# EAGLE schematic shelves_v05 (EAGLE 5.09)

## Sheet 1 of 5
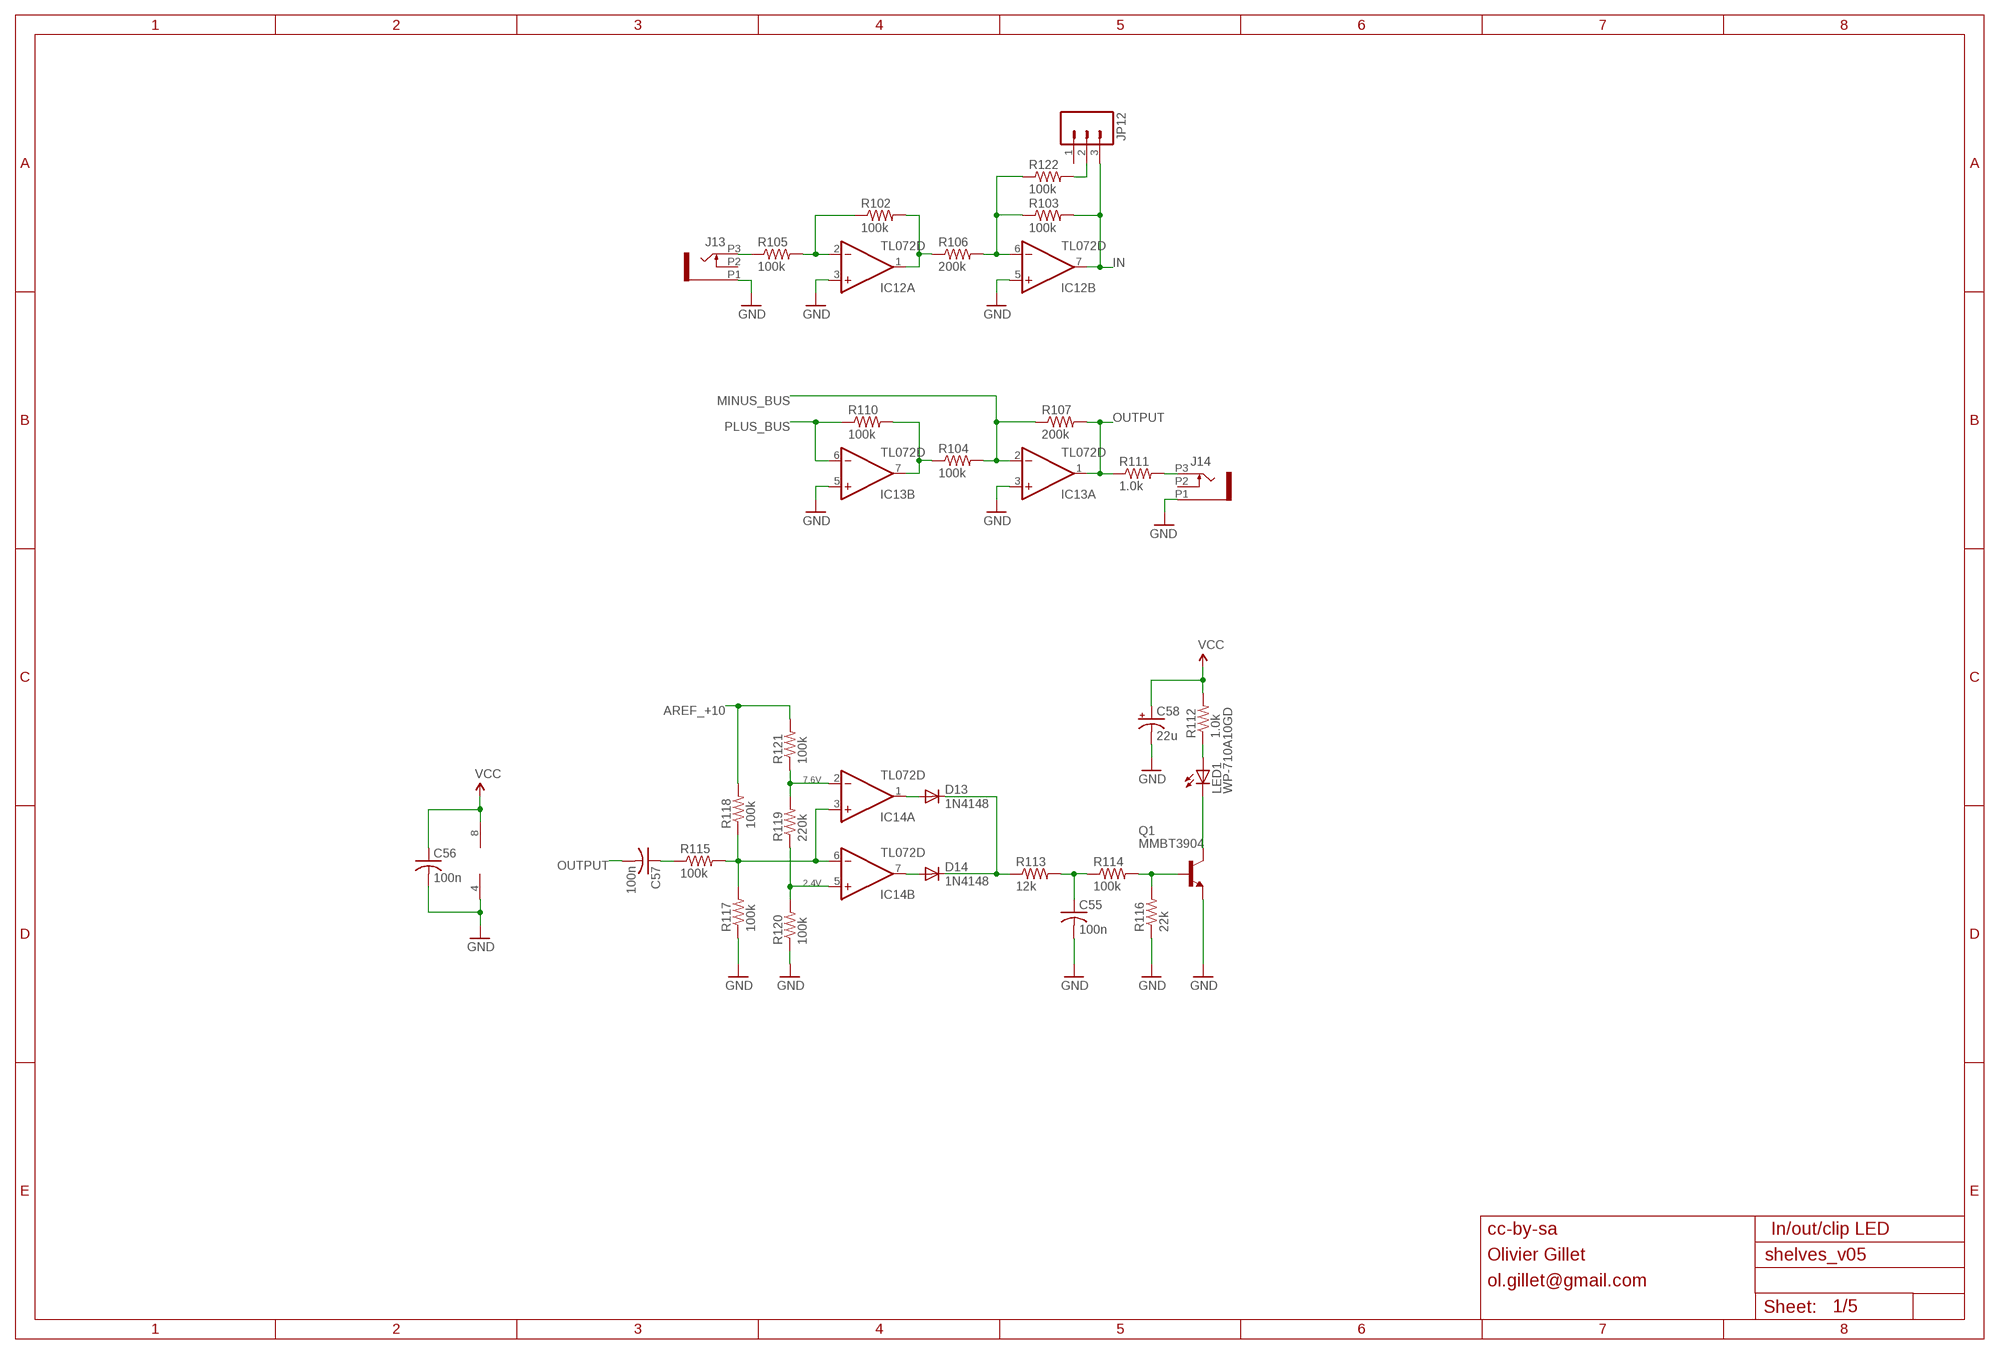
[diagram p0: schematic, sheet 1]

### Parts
C55  100n  C-USC0603  [C0603]
C56  100n  C-USC0603  [C0603]
C57  100n  C-USC0603  [C0603]
C58  22u  CPOL-USC  [PANASONIC_C]
D13  1N4148  DIODE-SOD323-W  [SOD323-W]
D14  1N4148  DIODE-SOD323-W  [SOD323-W]
IC12  TL072D  [SO08]
IC13  TL072D  [SO08]
IC14  TL072D  [SO08]
J13  PJ301_THONKICONN6  [WQP_PJ_301M6]
J14  PJ301_THONKICONN6  [WQP_PJ_301M6]
JP12  M03PTH  [1X03]
LED1  WP-710A10GD  LED3MM  [LED3MM]
Q1  MMBT3904  MMBT3904LT1-NPN-SOT23-BEC  [SOT23-BEC]
R102  100k  R-US_R0603  [R0603]
R103  100k  R-US_R0603  [R0603]
R104  100k  R-US_R0603  [R0603]
R105  100k  R-US_R0603  [R0603]
R106  200k  R-US_R0603  [R0603]
R107  200k  R-US_R0603  [R0603]
R110  100k  R-US_R0603  [R0603]
R111  1.0k  R-US_R0603  [R0603]
R112  1.0k  R-US_R0603  [R0603]
R113  12k  R-US_R0603  [R0603]
R114  100k  R-US_R0603  [R0603]
R115  100k  R-US_R0603  [R0603]
R116  22k  R-US_R0603  [R0603]
R117  100k  R-US_R0603  [R0603]
R118  100k  R-US_R0603  [R0603]
R119  220k  R-US_R0603  [R0603]
R120  100k  R-US_R0603  [R0603]
R121  100k  R-US_R0603  [R0603]
R122  100k  R-US_R0603  [R0603]

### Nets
AREF_+10: R118.2 R121.2 ; also sheet 2,3,4,5
GND: C55.2 C56.2 C58.- IC12.3(A:+IN) IC12.5(B:+IN) IC13.3(A:+IN) IC13.5(B:+IN) IC14.4(P:V-) J13.P1 J14.P1 Q1.E R116.1 R117.1 R120.1 ; also sheet 2,3,4,5
IN: IC12.7(B:OUT) JP12.3 R103.2 ; also sheet 2,3,4
IN_INV: IC12.1(A:OUT) R102.2 R106.1
IN_INV1: IC13.7(B:OUT) R104.1 R110.2
J_IN: J13.P3 R105.1
MINUS_BUS: IC13.2(A:-IN) R104.2 R107.1 ; also sheet 2,3,4
N$6: JP12.2 R122.2
N$9: IC12.2(A:-IN) R102.1 R105.2
N$30: IC12.6(B:-IN) R103.1 R106.2 R122.1
N$60: LED1.K(C) Q1.C
N$93: J14.P3 R111.2
N$94: C57.1 R115.1
N$96: IC14.3(A:+IN) IC14.6(B:-IN) R115.2 R117.2 R118.1
N$97: IC14.2(A:-IN) R119.2 R121.1
N$98: C55.1 R113.2 R114.1
N$99: IC14.5(B:+IN) R119.1 R120.2
N$100: D13.A IC14.1(A:OUT)
N$101: D14.A IC14.7(B:OUT)
N$102: D13.C D14.C R113.1
N$103: LED1.A R112.1
N$104: Q1.B R114.2 R116.2
OUTPUT: C57.2 IC13.1(A:OUT) R107.2 R111.1
PLUS_BUS: IC13.6(B:-IN) R110.1 ; also sheet 2,3,4
VCC: C56.1 C58.+ IC14.8(P:V+) R112.2 ; also sheet 2,3,4,5
Unconnected: J13.P2 J14.P2 JP12.1

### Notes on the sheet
- 7.6V
- 2.4V
- cc-by-sa | In/out/clip LED
- Olivier Gillet
- ol.gillet@gmail.com

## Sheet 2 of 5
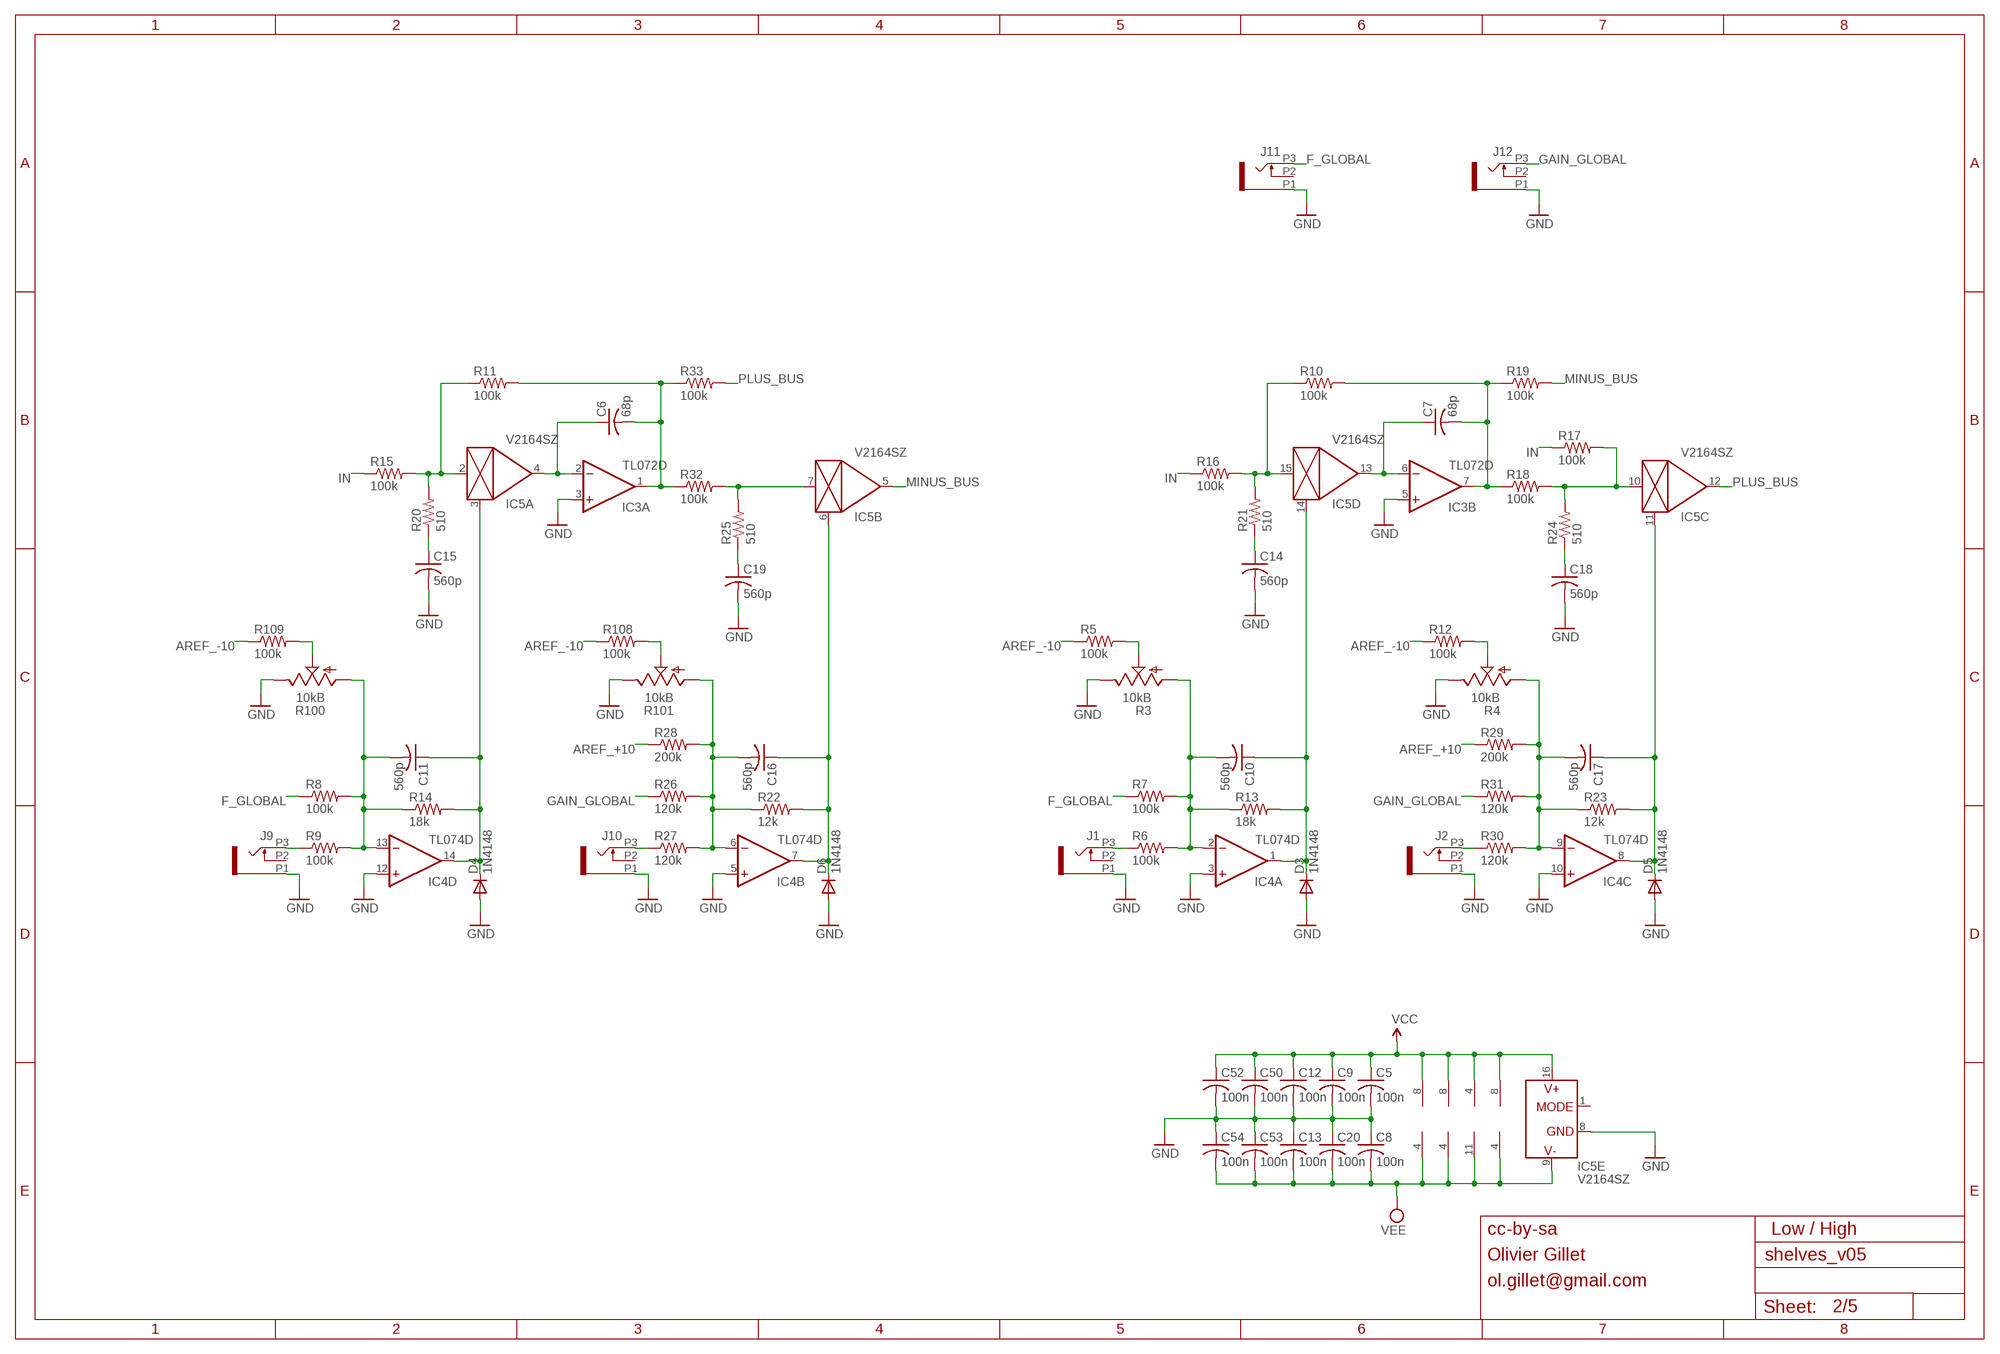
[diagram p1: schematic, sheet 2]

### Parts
C5  100n  C-USC0603  [C0603]
C6  68p  C-USC0603  [C0603]
C7  68p  C-USC0603  [C0603]
C8  100n  C-USC0603  [C0603]
C9  100n  C-USC0603  [C0603]
C10  560p  C-USC0603  [C0603]
C11  560p  C-USC0603  [C0603]
C12  100n  C-USC0603  [C0603]
C13  100n  C-USC0603  [C0603]
C14  560p  C-USC0603  [C0603]
C15  560p  C-USC0603  [C0603]
C16  560p  C-USC0603  [C0603]
C17  560p  C-USC0603  [C0603]
C18  560p  C-USC0603  [C0603]
C19  560p  C-USC0603  [C0603]
C20  100n  C-USC0603  [C0603]
C50  100n  C-USC0603  [C0603]
C52  100n  C-USC0603  [C0603]
C53  100n  C-USC0603  [C0603]
C54  100n  C-USC0603  [C0603]
D3  1N4148  DIODE-SOD323-W  [SOD323-W]
D4  1N4148  DIODE-SOD323-W  [SOD323-W]
D5  1N4148  DIODE-SOD323-W  [SOD323-W]
D6  1N4148  DIODE-SOD323-W  [SOD323-W]
IC3  TL072D  [SO08]
IC4  TL074D  [SO14]
IC5  V2164SZ  SSM2164S  [SOIC16N]
J1  PJ301_THONKICONN6  [WQP_PJ_301M6]
J2  PJ301_THONKICONN6  [WQP_PJ_301M6]
J9  PJ301_THONKICONN6  [WQP_PJ_301M6]
J10  PJ301_THONKICONN6  [WQP_PJ_301M6]
J11  PJ301_THONKICONN6  [WQP_PJ_301M6]
J12  PJ301_THONKICONN6  [WQP_PJ_301M6]
R3  10kB  POT_USVERTICAL_PS  [ALPS_POT_VERTICAL_PS]
R4  10kB  POT_USVERTICAL_PS  [ALPS_POT_VERTICAL_PS]
R5  100k  R-US_R0603  [R0603]
R6  100k  R-US_R0603  [R0603]
R7  100k  R-US_R0603  [R0603]
R8  100k  R-US_R0603  [R0603]
R9  100k  R-US_R0603  [R0603]
R10  100k  R-US_R0603  [R0603]
R11  100k  R-US_R0603  [R0603]
R12  100k  R-US_R0603  [R0603]
R13  18k  R-US_R0603  [R0603]
R14  18k  R-US_R0603  [R0603]
R15  100k  R-US_R0603  [R0603]
R16  100k  R-US_R0603  [R0603]
R17  100k  R-US_R0603  [R0603]
R18  100k  R-US_R0603  [R0603]
R19  100k  R-US_R0603  [R0603]
R20  510  R-US_R0603  [R0603]
R21  510  R-US_R0603  [R0603]
R22  12k  R-US_R0603  [R0603]
R23  12k  R-US_R0603  [R0603]
R24  510  R-US_R0603  [R0603]
R25  510  R-US_R0603  [R0603]
R26  120k  R-US_R0603  [R0603]
R27  120k  R-US_R0603  [R0603]
R28  200k  R-US_R0603  [R0603]
R29  200k  R-US_R0603  [R0603]
R30  120k  R-US_R0603  [R0603]
R31  120k  R-US_R0603  [R0603]
R32  100k  R-US_R0603  [R0603]
R33  100k  R-US_R0603  [R0603]
R100  10kB  POT_USVERTICAL_PS  [ALPS_POT_VERTICAL_PS]
R101  10kB  POT_USVERTICAL_PS  [ALPS_POT_VERTICAL_PS]
R108  100k  R-US_R0603  [R0603]
R109  100k  R-US_R0603  [R0603]

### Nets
AREF_+10: R28.1 R29.1 ; also sheet 1,3,4,5
AREF_-10: R5.1 R12.1 R108.1 R109.1 ; also sheet 3,4,5
F_GLOBAL: J11.P3 R7.1 R8.1 ; also sheet 3,4
GAIN_GLOBAL: J12.P3 R26.1 R31.1 ; also sheet 3,4
GND: C5.2 C8.1 C9.2 C12.2 C13.1 C14.2 C15.2 C18.2 C19.2 C20.1 C50.2 C52.2 C53.1 C54.1 D3.A D4.A D5.A D6.A IC3.3(A:+IN) IC3.5(B:+IN) IC4.3(A:+IN) IC4.5(B:+IN) IC4.10(C:+IN) IC4.12(D:+IN) IC5.8(E:GND) J1.P1 J2.P1 J9.P1 J10.P1 J11.P1 J12.P1 R3.P$1(E) R4.P$1(E) R100.P$1(E) R101.P$1(E) ; also sheet 1,3,4,5
IN: R15.1 R16.1 R17.1 ; also sheet 1,3,4
J_HF_CV: J2.P3 R30.1
J_HF_F: J1.P3 R6.1
J_LF_CV: J10.P3 R27.1
J_LF_F: J9.P3 R9.1
LP: C6.2 IC3.1(A:OUT) R11.2 R32.1 R33.1
LP1: C7.2 IC3.7(B:OUT) R10.2 R18.1 R19.1
MINUS_BUS: IC5.5(B:OUT) R19.2 ; also sheet 1,3,4
N$1: IC5.2(A:IN) R11.1 R15.2 R20.2
N$2: C19.1 R25.1
N$3: C11.1 D4.C IC4.14(D:OUT) IC5.3(A:CTRL) R14.2
N$4: C6.1 IC3.2(A:-IN) IC5.4(A:OUT)
N$5: C14.1 R21.1
N$7: C16.1 D6.C IC4.7(B:OUT) IC5.6(B:CTRL) R22.2
N$10: C15.1 R20.1
N$12: R100.P$2(S) R109.2
N$13: C16.2 IC4.6(B:-IN) R22.1 R26.2 R27.2 R28.2 R101.P$3(A)
N$15: R101.P$2(S) R108.2
N$16: IC5.15(D:IN) R10.1 R16.2 R21.2
N$17: IC5.7(B:IN) R25.2 R32.2
N$18: C11.2 IC4.13(D:-IN) R8.2 R9.2 R14.1 R100.P$3(A)
N$19: C7.1 IC3.6(B:-IN) IC5.13(D:OUT)
N$21: R3.P$2(S) R5.2
N$22: C17.1 D5.C IC4.8(C:OUT) IC5.11(C:CTRL) R23.2
N$23: C17.2 IC4.9(C:-IN) R4.P$3(A) R23.1 R29.2 R30.2 R31.2
N$26: R4.P$2(S) R12.2
N$27: C10.2 IC4.2(A:-IN) R3.P$3(A) R6.2 R7.2 R13.1
N$28: C18.1 R24.1
N$29: IC5.10(C:IN) R17.2 R18.2 R24.2
N$31: C10.1 D3.C IC4.1(A:OUT) IC5.14(D:CTRL) R13.2
PLUS_BUS: IC5.12(C:OUT) R33.2 ; also sheet 1,3,4
VCC: C5.1 C9.1 C12.1 C50.1 C52.1 IC3.8(P:V+) IC4.4(P:V+) IC5.16(E:V+) IC12.8(P:V+) IC13.8(P:V+) ; also sheet 1,3,4,5
VEE: C8.2 C13.2 C20.2 C53.2 C54.2 IC3.4(P:V-) IC4.11(P:V-) IC5.9(E:V-) IC12.4(P:V-) IC13.4(P:V-) ; also sheet 3,4,5
Unconnected: IC5.1(E:MODE) J1.P2 J2.P2 J9.P2 J10.P2 J11.P2 J12.P2

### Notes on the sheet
- cc-by-sa | Low / High
- Olivier Gillet
- ol.gillet@gmail.com

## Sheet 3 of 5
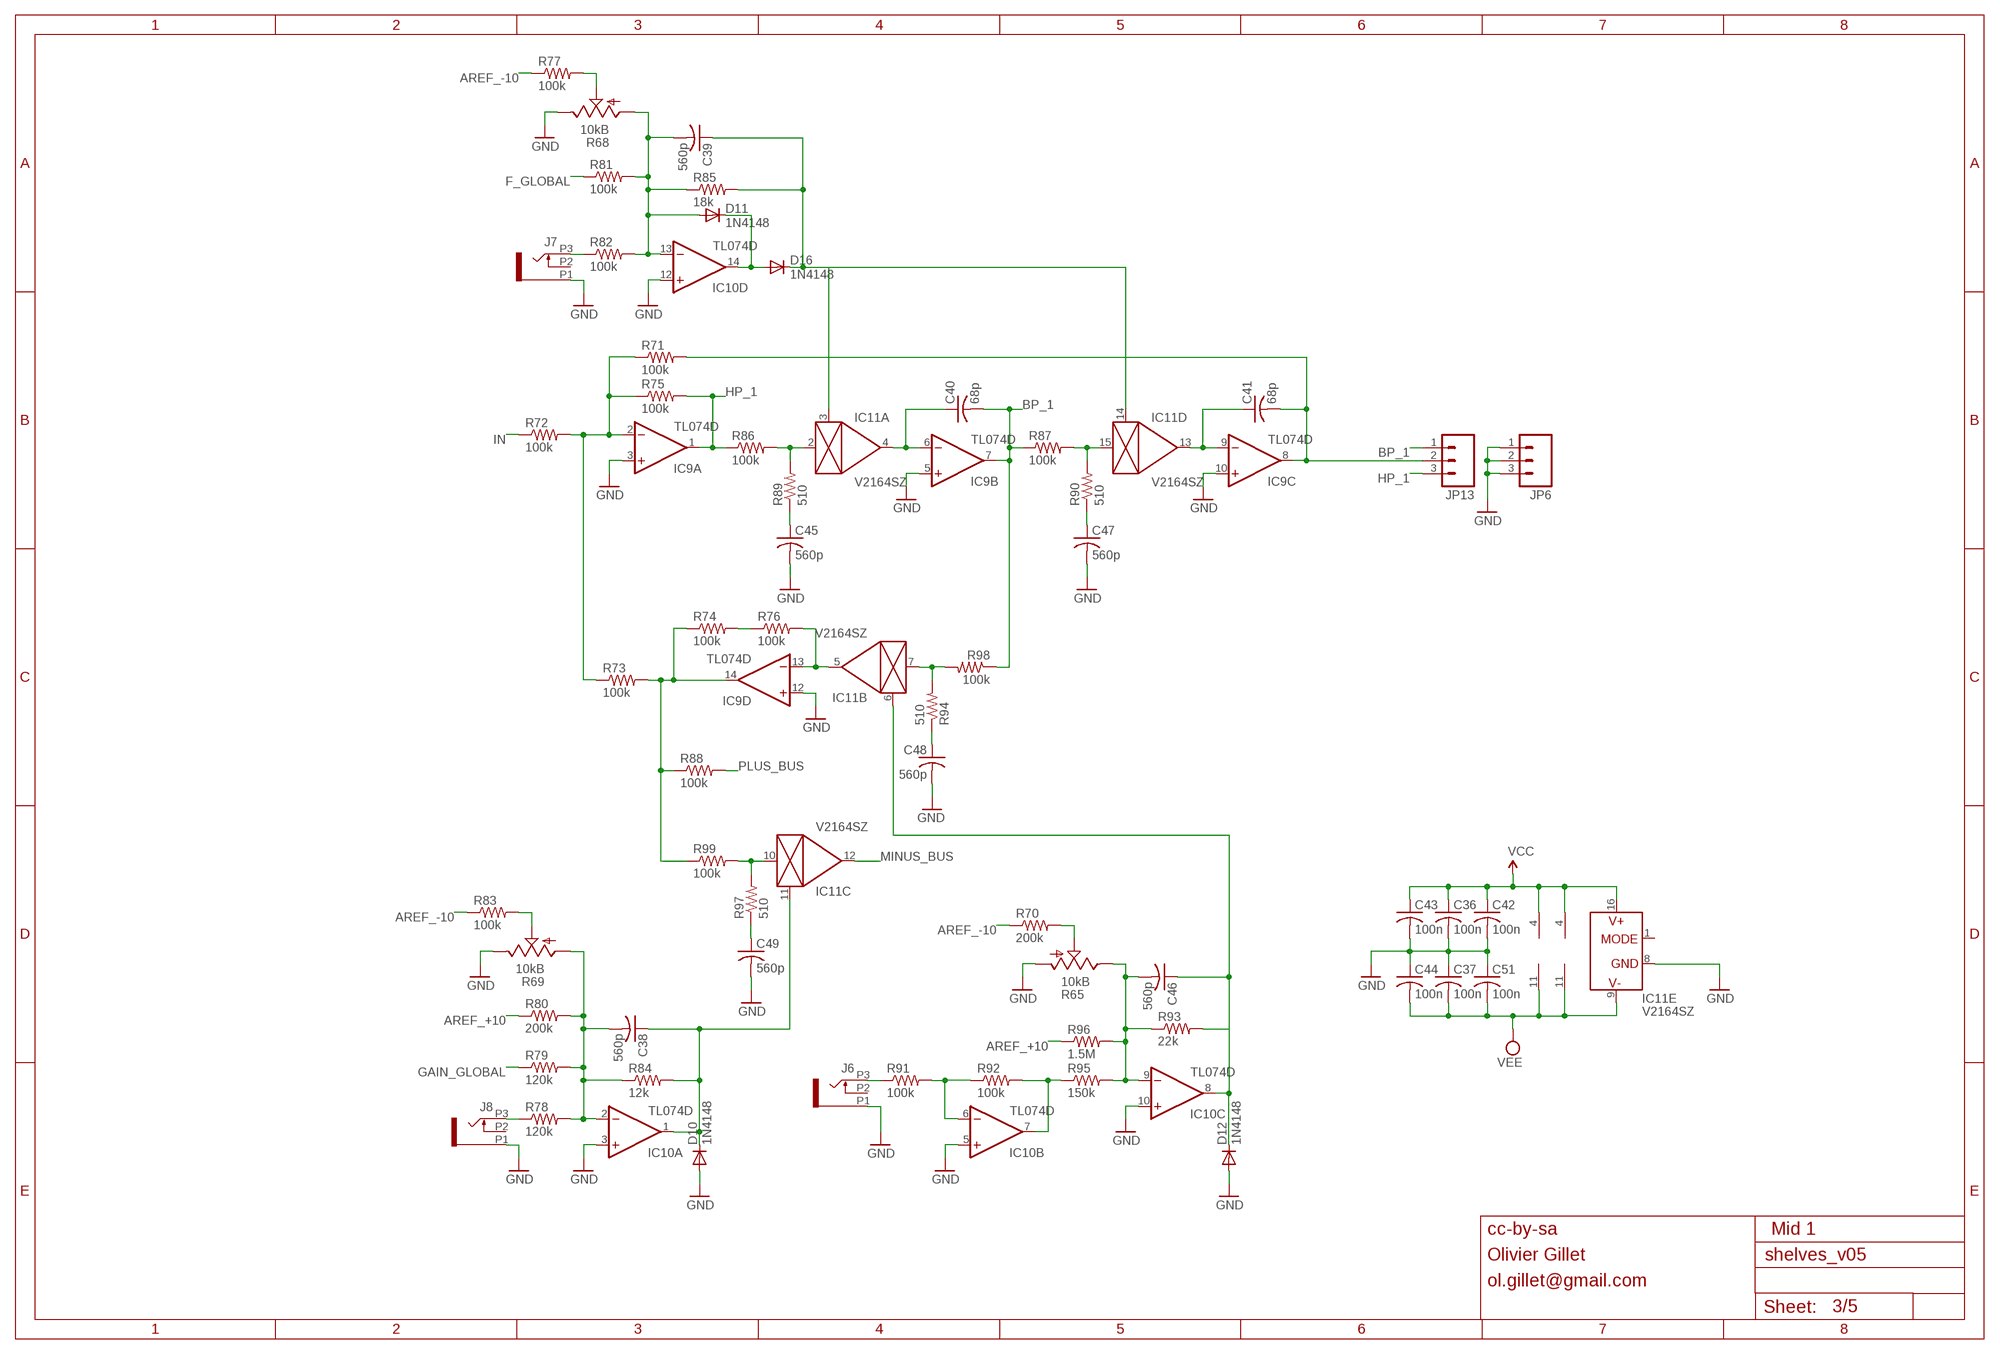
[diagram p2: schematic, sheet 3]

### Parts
C36  100n  C-USC0603  [C0603]
C37  100n  C-USC0603  [C0603]
C38  560p  C-USC0603  [C0603]
C39  560p  C-USC0603  [C0603]
C40  68p  C-USC0603  [C0603]
C41  68p  C-USC0603  [C0603]
C42  100n  C-USC0603  [C0603]
C43  100n  C-USC0603  [C0603]
C44  100n  C-USC0603  [C0603]
C45  560p  C-USC0603  [C0603]
C46  560p  C-USC0603  [C0603]
C47  560p  C-USC0603  [C0603]
C48  560p  C-USC0603  [C0603]
C49  560p  C-USC0603  [C0603]
C51  100n  C-USC0603  [C0603]
D10  1N4148  DIODE-SOD323-W  [SOD323-W]
D11  1N4148  DIODE-SOD323-W  [SOD323-W]
D12  1N4148  DIODE-SOD323-W  [SOD323-W]
D16  1N4148  DIODE-SOD323-W  [SOD323-W]
IC9  TL074D  [SO14]
IC10  TL074D  [SO14]
IC11  V2164SZ  SSM2164S  [SOIC16N]
J6  PJ301_THONKICONN6  [WQP_PJ_301M6]
J7  PJ301_THONKICONN6  [WQP_PJ_301M6]
J8  PJ301_THONKICONN6  [WQP_PJ_301M6]
JP6  M03PTH  [1X03]
JP13  M03PTH  [1X03]
R65  10kB  POT_USVERTICAL  [ALPS_POT_VERTICAL]
R68  10kB  POT_USVERTICAL_PS  [ALPS_POT_VERTICAL_PS]
R69  10kB  POT_USVERTICAL_PS  [ALPS_POT_VERTICAL_PS]
R70  200k  R-US_R0603  [R0603]
R71  100k  R-US_R0603  [R0603]
R72  100k  R-US_R0603  [R0603]
R73  100k  R-US_R0603  [R0603]
R74  100k  R-US_R0603  [R0603]
R75  100k  R-US_R0603  [R0603]
R76  100k  R-US_R0603  [R0603]
R77  100k  R-US_R0603  [R0603]
R78  120k  R-US_R0603  [R0603]
R79  120k  R-US_R0603  [R0603]
R80  200k  R-US_R0603  [R0603]
R81  100k  R-US_R0603  [R0603]
R82  100k  R-US_R0603  [R0603]
R83  100k  R-US_R0603  [R0603]
R84  12k  R-US_R0603  [R0603]
R85  18k  R-US_R0603  [R0603]
R86  100k  R-US_R0603  [R0603]
R87  100k  R-US_R0603  [R0603]
R88  100k  R-US_R0603  [R0603]
R89  510  R-US_R0603  [R0603]
R90  510  R-US_R0603  [R0603]
R91  100k  R-US_R0603  [R0603]
R92  100k  R-US_R0603  [R0603]
R93  22k  R-US_R0603  [R0603]
R94  510  R-US_R0603  [R0603]
R95  150k  R-US_R0603  [R0603]
R96  1.5M  R-US_R0603  [R0603]
R97  510  R-US_R0603  [R0603]
R98  100k  R-US_R0603  [R0603]
R99  100k  R-US_R0603  [R0603]

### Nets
AREF_+10: R80.1 R96.1 ; also sheet 1,2,4,5
AREF_-10: R70.1 R77.1 R83.1 ; also sheet 2,4,5
BP_1: C40.2 IC9.7(B:OUT) JP13.1 R87.1 R98.1
F_GLOBAL: R81.1 ; also sheet 2,4
GAIN_GLOBAL: R79.1 ; also sheet 2,4
GND: C36.2 C37.1 C42.2 C43.2 C44.1 C45.2 C47.2 C48.2 C49.2 C51.1 D10.A D12.A IC9.3(A:+IN) IC9.5(B:+IN) IC9.10(C:+IN) IC9.12(D:+IN) IC10.3(A:+IN) IC10.5(B:+IN) IC10.10(C:+IN) IC10.12(D:+IN) IC11.8(E:GND) J6.P1 J7.P1 J8.P1 JP6.1 JP6.2 JP6.3 R65.P$3(A) R68.P$1(E) R69.P$1(E) ; also sheet 1,2,4,5
HP_1: IC9.1(A:OUT) JP13.3 R75.2 R86.1
IN: R72.1 ; also sheet 1,2,4
MID1_F2: C39.1 D16.C IC11.3(A:CTRL) IC11.14(D:CTRL) R85.2
MINUS_BUS: IC11.12(C:OUT) ; also sheet 1,2,4
N$8: D11.C D16.A IC10.14(D:OUT)
N$11: IC10.7(B:OUT) R92.2 R95.1
N$25: C45.1 R89.1
N$32: J7.P3 R82.1
N$33: R68.P$2(S) R77.2
N$34: C38.1 D10.C IC10.1(A:OUT) IC11.11(C:CTRL) R84.2
N$35: C38.2 IC10.2(A:-IN) R69.P$3(A) R78.2 R79.2 R80.2 R84.1
N$36: J8.P3 R78.1
N$37: R69.P$2(S) R83.2
N$38: C39.2 D11.A IC10.13(D:-IN) R68.P$3(A) R81.2 R82.2 R85.1
N$39: C49.1 R97.1
N$40: IC11.10(C:IN) R97.2 R99.2
N$41: IC9.2(A:-IN) R71.1 R72.2 R73.1 R75.1
N$43: IC11.2(A:IN) R86.2 R89.2
N$44: C40.1 IC9.6(B:-IN) IC11.4(A:OUT)
N$45: C47.1 R90.1
N$48: IC11.15(D:IN) R87.2 R90.2
N$49: C41.1 IC9.9(C:-IN) IC11.13(D:OUT)
N$50: C41.2 IC9.8(C:OUT) JP13.2 R71.2
N$51: C48.1 R94.1
N$52: IC11.7(B:IN) R94.2 R98.2
N$53: IC9.13(D:-IN) IC11.5(B:OUT) R76.2
N$54: R74.2 R76.1
N$55: IC9.14(D:OUT) R73.2 R74.1 R88.1 R99.1
N$57: C46.1 D12.C IC10.8(C:OUT) IC11.6(B:CTRL) R93.2
N$58: C46.2 IC10.9(C:-IN) R65.P$1(E) R93.1 R95.2 R96.2
N$59: R65.P$2(S) R70.2
N$62: J6.P3 R91.1
N$91: IC10.6(B:-IN) R91.2 R92.1
PLUS_BUS: R88.2 ; also sheet 1,2,4
VCC: C36.1 C42.1 C43.1 IC9.4(P:V+) IC10.4(P:V+) IC11.16(E:V+) ; also sheet 1,2,4,5
VEE: C37.2 C44.2 C51.2 IC9.11(P:V-) IC10.11(P:V-) IC11.9(E:V-) ; also sheet 2,4,5
Unconnected: IC11.1(E:MODE) J6.P2 J7.P2 J8.P2

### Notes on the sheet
- cc-by-sa | Mid 1
- Olivier Gillet
- ol.gillet@gmail.com

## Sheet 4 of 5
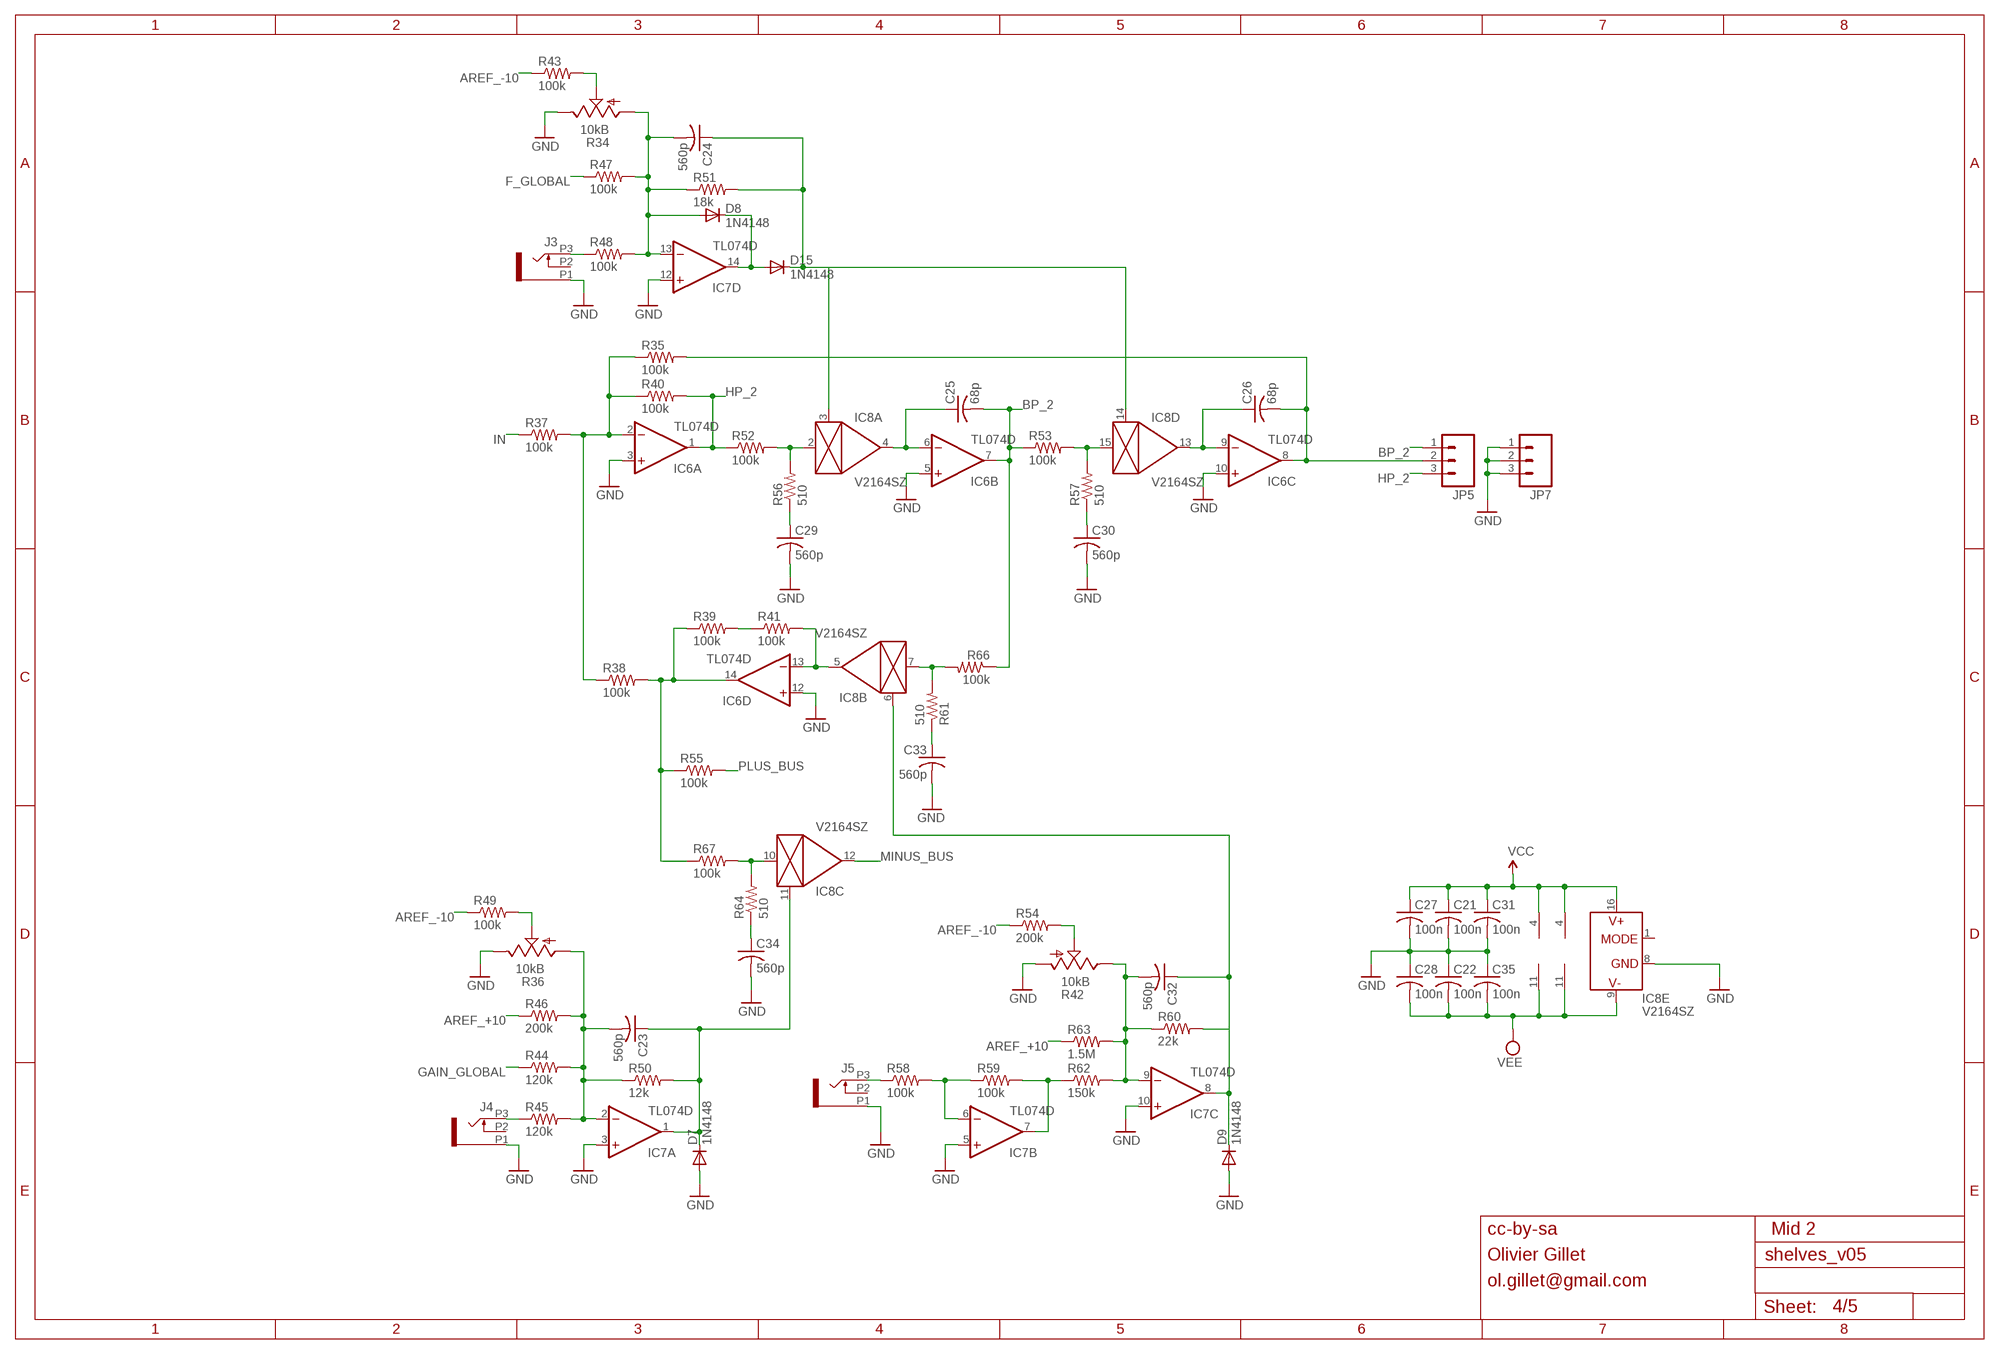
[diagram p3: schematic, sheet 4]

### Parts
C21  100n  C-USC0603  [C0603]
C22  100n  C-USC0603  [C0603]
C23  560p  C-USC0603  [C0603]
C24  560p  C-USC0603  [C0603]
C25  68p  C-USC0603  [C0603]
C26  68p  C-USC0603  [C0603]
C27  100n  C-USC0603  [C0603]
C28  100n  C-USC0603  [C0603]
C29  560p  C-USC0603  [C0603]
C30  560p  C-USC0603  [C0603]
C31  100n  C-USC0603  [C0603]
C32  560p  C-USC0603  [C0603]
C33  560p  C-USC0603  [C0603]
C34  560p  C-USC0603  [C0603]
C35  100n  C-USC0603  [C0603]
D7  1N4148  DIODE-SOD323-W  [SOD323-W]
D8  1N4148  DIODE-SOD323-W  [SOD323-W]
D9  1N4148  DIODE-SOD323-W  [SOD323-W]
D15  1N4148  DIODE-SOD323-W  [SOD323-W]
IC6  TL074D  [SO14]
IC7  TL074D  [SO14]
IC8  V2164SZ  SSM2164S  [SOIC16N]
J3  PJ301_THONKICONN6  [WQP_PJ_301M6]
J4  PJ301_THONKICONN6  [WQP_PJ_301M6]
J5  PJ301_THONKICONN6  [WQP_PJ_301M6]
JP5  M03PTH  [1X03]
JP7  M03PTH  [1X03]
R34  10kB  POT_USVERTICAL_PS  [ALPS_POT_VERTICAL_PS]
R35  100k  R-US_R0603  [R0603]
R36  10kB  POT_USVERTICAL_PS  [ALPS_POT_VERTICAL_PS]
R37  100k  R-US_R0603  [R0603]
R38  100k  R-US_R0603  [R0603]
R39  100k  R-US_R0603  [R0603]
R40  100k  R-US_R0603  [R0603]
R41  100k  R-US_R0603  [R0603]
R42  10kB  POT_USVERTICAL  [ALPS_POT_VERTICAL]
R43  100k  R-US_R0603  [R0603]
R44  120k  R-US_R0603  [R0603]
R45  120k  R-US_R0603  [R0603]
R46  200k  R-US_R0603  [R0603]
R47  100k  R-US_R0603  [R0603]
R48  100k  R-US_R0603  [R0603]
R49  100k  R-US_R0603  [R0603]
R50  12k  R-US_R0603  [R0603]
R51  18k  R-US_R0603  [R0603]
R52  100k  R-US_R0603  [R0603]
R53  100k  R-US_R0603  [R0603]
R54  200k  R-US_R0603  [R0603]
R55  100k  R-US_R0603  [R0603]
R56  510  R-US_R0603  [R0603]
R57  510  R-US_R0603  [R0603]
R58  100k  R-US_R0603  [R0603]
R59  100k  R-US_R0603  [R0603]
R60  22k  R-US_R0603  [R0603]
R61  510  R-US_R0603  [R0603]
R62  150k  R-US_R0603  [R0603]
R63  1.5M  R-US_R0603  [R0603]
R64  510  R-US_R0603  [R0603]
R66  100k  R-US_R0603  [R0603]
R67  100k  R-US_R0603  [R0603]

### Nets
AREF_+10: R46.1 R63.1 ; also sheet 1,2,3,5
AREF_-10: R43.1 R49.1 R54.1 ; also sheet 2,3,5
BP_2: C25.2 IC6.7(B:OUT) JP5.1 R53.1 R66.1
F_GLOBAL: R47.1 ; also sheet 2,3
GAIN_GLOBAL: R44.1 ; also sheet 2,3
GND: C21.2 C22.1 C27.2 C28.1 C29.2 C30.2 C31.2 C33.2 C34.2 C35.1 D7.A D9.A IC6.3(A:+IN) IC6.5(B:+IN) IC6.10(C:+IN) IC6.12(D:+IN) IC7.3(A:+IN) IC7.5(B:+IN) IC7.10(C:+IN) IC7.12(D:+IN) IC8.8(E:GND) J3.P1 J4.P1 J5.P1 JP7.1 JP7.2 JP7.3 R34.P$1(E) R36.P$1(E) R42.P$3(A) ; also sheet 1,2,3,5
HP_2: IC6.1(A:OUT) JP5.3 R40.2 R52.1
IN: R37.1 ; also sheet 1,2,3
MID1_F1: C24.1 D15.C IC8.3(A:CTRL) IC8.14(D:CTRL) R51.2
MINUS_BUS: IC8.12(C:OUT) ; also sheet 1,2,3
N$14: D8.C D15.A IC7.14(D:OUT)
N$47: C29.1 R56.1
N$61: IC7.7(B:OUT) R59.2 R62.1
N$63: J3.P3 R48.1
N$65: R34.P$2(S) R43.2
N$66: C23.1 D7.C IC7.1(A:OUT) IC8.11(C:CTRL) R50.2
N$67: C23.2 IC7.2(A:-IN) R36.P$3(A) R44.2 R45.2 R46.2 R50.1
N$68: J4.P3 R45.1
N$69: R36.P$2(S) R49.2
N$70: C24.2 D8.A IC7.13(D:-IN) R34.P$3(A) R47.2 R48.2 R51.1
N$71: C34.1 R64.1
N$72: IC8.10(C:IN) R64.2 R67.2
N$73: IC6.2(A:-IN) R35.1 R37.2 R38.1 R40.1
N$75: IC8.2(A:IN) R52.2 R56.2
N$76: C25.1 IC6.6(B:-IN) IC8.4(A:OUT)
N$77: C30.1 R57.1
N$79: IC8.15(D:IN) R53.2 R57.2
N$80: C26.1 IC6.9(C:-IN) IC8.13(D:OUT)
N$81: C26.2 IC6.8(C:OUT) JP5.2 R35.2
N$82: C33.1 R61.1
N$83: IC8.7(B:IN) R61.2 R66.2
N$84: IC6.13(D:-IN) IC8.5(B:OUT) R41.2
N$85: R39.2 R41.1
N$86: IC6.14(D:OUT) R38.2 R39.1 R55.1 R67.1
N$87: C32.1 D9.C IC7.8(C:OUT) IC8.6(B:CTRL) R60.2
N$88: C32.2 IC7.9(C:-IN) R42.P$1(E) R60.1 R62.2 R63.2
N$89: IC7.6(B:-IN) R58.2 R59.1
N$90: R42.P$2(S) R54.2
N$92: J5.P3 R58.1
PLUS_BUS: R55.2 ; also sheet 1,2,3
VCC: C21.1 C27.1 C31.1 IC6.4(P:V+) IC7.4(P:V+) IC8.16(E:V+) ; also sheet 1,2,3,5
VEE: C22.2 C28.2 C35.2 IC6.11(P:V-) IC7.11(P:V-) IC8.9(E:V-) ; also sheet 2,3,5
Unconnected: IC8.1(E:MODE) J3.P2 J4.P2 J5.P2

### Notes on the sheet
- cc-by-sa | Mid 2
- Olivier Gillet
- ol.gillet@gmail.com

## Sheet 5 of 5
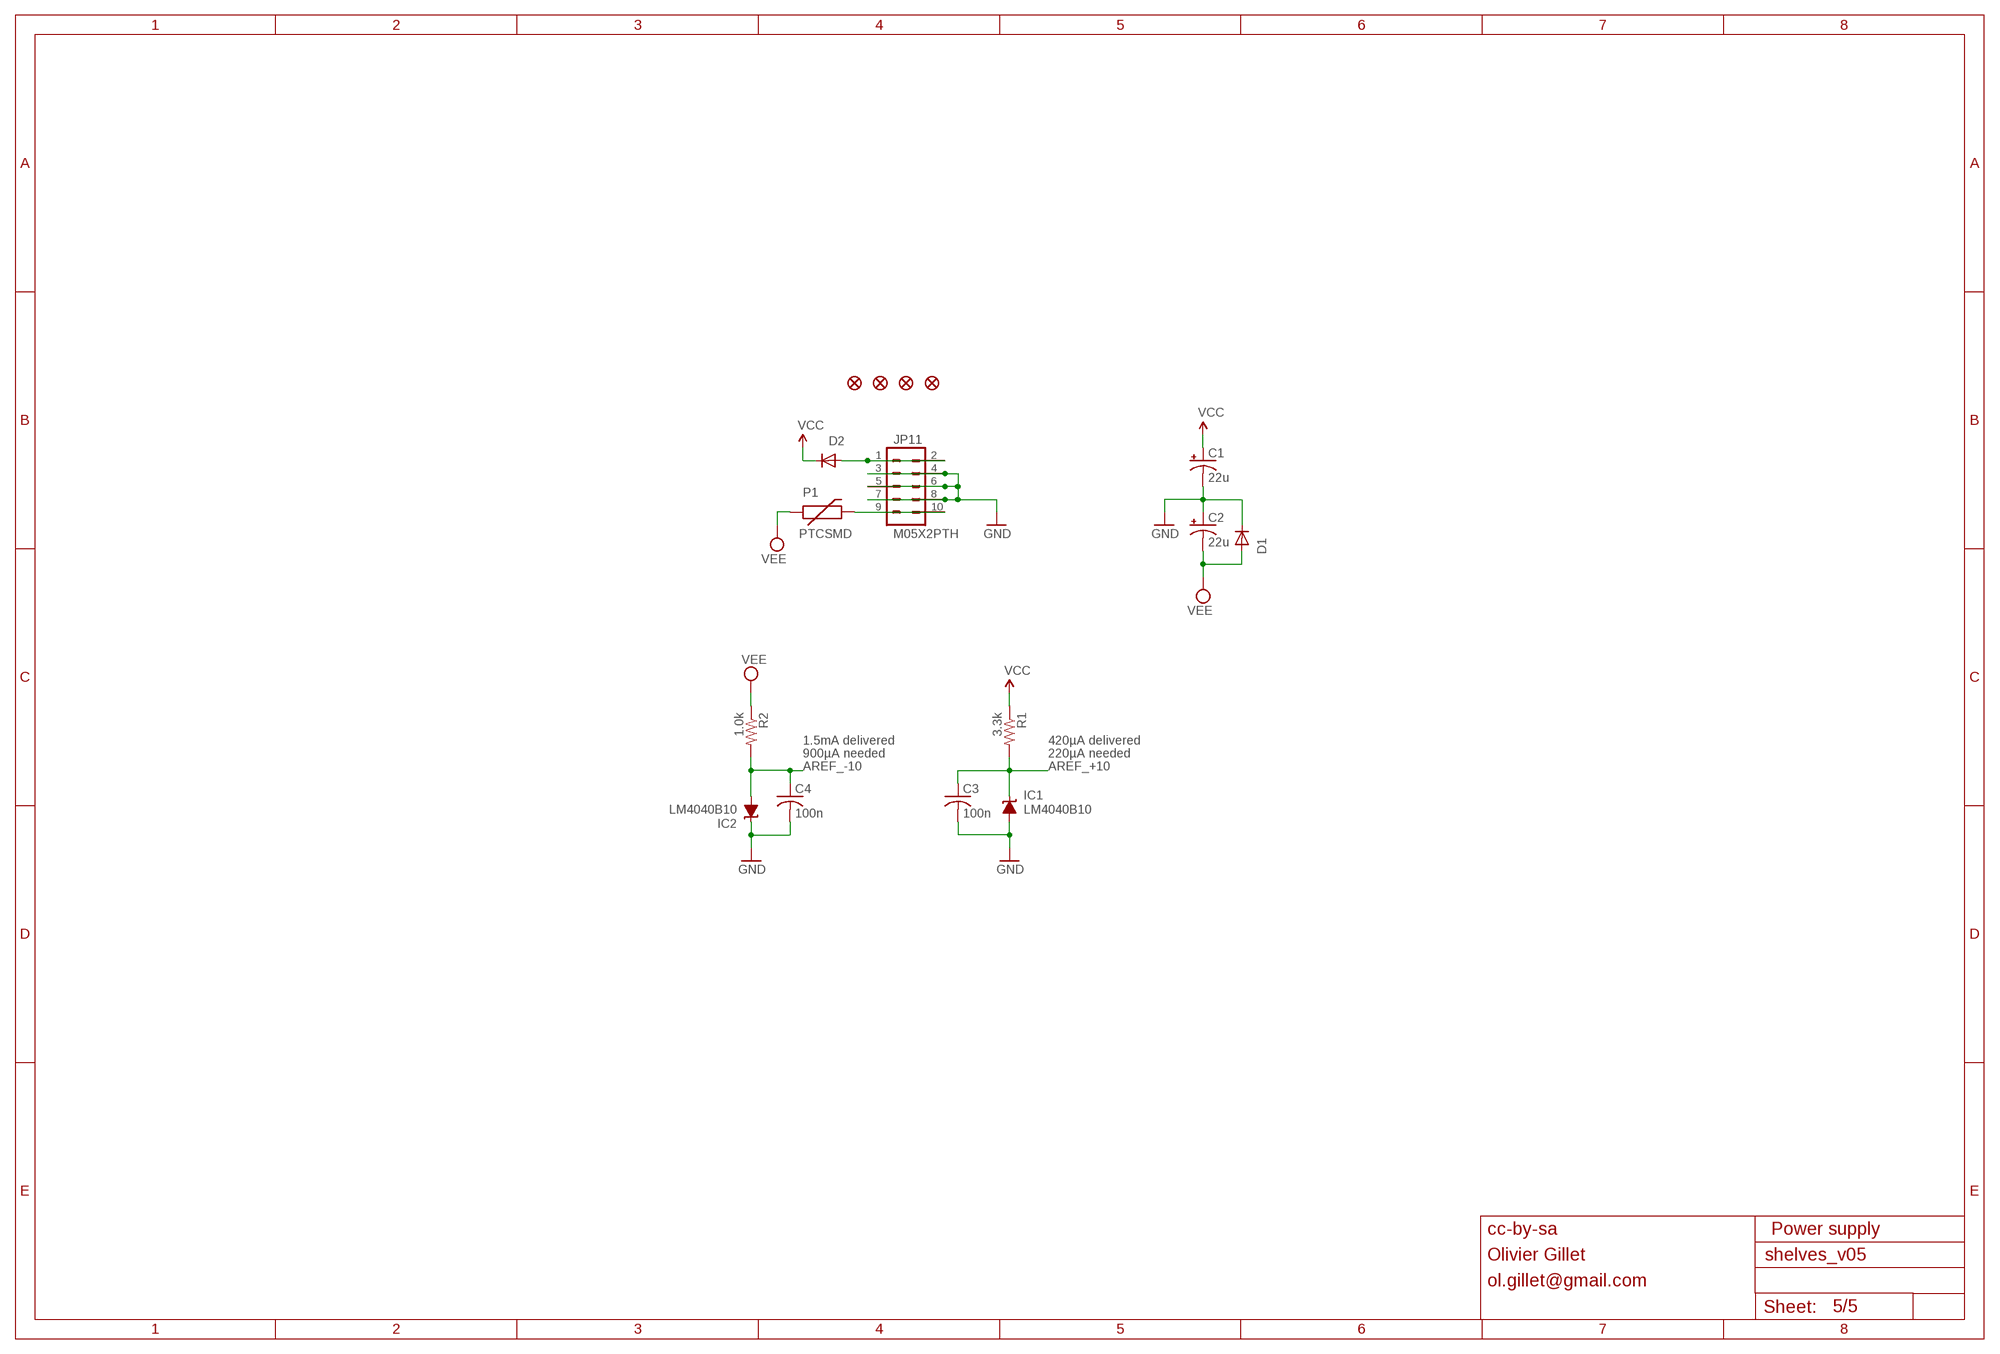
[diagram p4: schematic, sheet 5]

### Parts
C1  22u  CPOL-USC  [PANASONIC_C]
C2  22u  CPOL-USC  [PANASONIC_C]
C3  100n  C-USC0603  [C0603]
C4  100n  C-USC0603  [C0603]
D1  1N5819HW  DIODE-SOD123  [SOD123]
D2  1N5819HW  DIODE-SOD123  [SOD123]
IC1  LM4040B10  LM4041B12DBZ  [DBZ_R-PDSO-G3]
IC2  LM4040B10  LM4041B12DBZ  [DBZ_R-PDSO-G3]
JP1  FIDUCIAL1X2  [FIDUCIAL-1X2]
JP2  FIDUCIAL1X2  [FIDUCIAL-1X2]
JP3  FIDUCIAL1X2  [FIDUCIAL-1X2]
JP4  FIDUCIAL1X2  [FIDUCIAL-1X2]
JP11  M05X2PTH  [AVR_ICSP]
P1  PTCSMD  [PTC-1206]
R1  3.3k  R-US_R0603  [R0603]
R2  1.0k  R-US_R0603  [R0603]

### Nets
AREF_+10: C3.1 IC1.1(C) R1.2 ; also sheet 1,2,3,4
AREF_-10: C4.1 IC2.2(A) R2.2 ; also sheet 2,3,4
GND: C1.- C2.+ C3.2 C4.2 D1.C IC1.2(A) IC2.1(C) JP11.3 JP11.4 JP11.5 JP11.6 JP11.7 JP11.8 ; also sheet 1,2,3,4
N$56: D2.A JP11.1 JP11.2
N$64: JP11.9 JP11.10 P1.2
VCC: C1.+ D2.C R1.1 ; also sheet 1,2,3,4
VEE: C2.- D1.A P1.1 R2.1 ; also sheet 2,3,4

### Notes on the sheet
- 1.5mA delivered | 420µA delivered
- 900µA needed | 220µA needed
- cc-by-sa | Power supply
- Olivier Gillet
- ol.gillet@gmail.com

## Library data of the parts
C1 C2 C58 = rcl:CPOL-US: POLARIZED CAPACITOR, American symbol
C3-C57 = rcl:C-US: CAPACITOR, American symbol
D1-D16 = diode:DIODE-: DIODE
IC1 IC2 = texas:LM4041: PRECISION MICROPOWER SHUNT VOLTAGE REFERENCE
IC3 IC12-IC14 = og-linear:TL072: OP AMP
IC4 IC6 IC7 IC9 IC10 = linear:TL074: OP AMP
IC5 IC8 IC11 = ssm2164:SSM2164
J1-J14 = og-pj301:PJ301_THONKICONN
JP1-JP4 = SparkFun:FIDUCIAL: Fiducial Alignment Points
JP5-JP7 JP12 JP13 = SparkFun:M03: Header 3 Standard 3-pin 0.1" header. Use with straight break away headers (SKU : PRT-00116), right angle break away headers (PRT-00553), swiss pins (PRT-00743), machine pins (PRT-00117), and female headers (PRT-00115). Molex polarized connector foot print use with SKU : PRT-08232 with associated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
JP11 = og-header:M05X2: Header 5x2 Standard 10-pin dual row 0.1" header. Commonly used with AVR-ISP. Use with Spark Fun Electronics SKU: PRT-00778
LED1 = led:LED: LED
P1 = SparkFun:PTC: Resettable Fuse PTC
Q1 = transistor:*-NPN-: NPN Transistror BF959 corrected 2008.03.06
R1 R2 R5-R33 R35 R37-R41 R43-R64 R66 R67 R70-R99 R102-R122 = rcl:R-US_: RESISTOR, American symbol
R3 R4 R34 R36 R42 R65 R68 R69 R100 R101 = pot-alps:POT_US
